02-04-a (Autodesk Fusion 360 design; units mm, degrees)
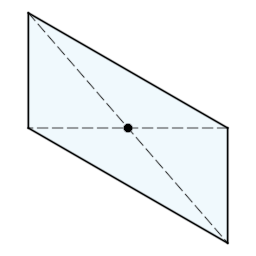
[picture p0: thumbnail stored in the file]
sketch "スケッチ" plane through (0, 0, 0) normal (0, 0, 1) x axis (1, 0, 0)
  line L1 (-50, 25) -> (50, 25)
  line L2 (-50, -25) -> (-50, 25)
  line L3 (50, -25) -> (-50, -25)
  line L4 (50, 25) -> (50, -25)
  line L5 (-50, -25) -> (50, 25)
  line L6 (50, -25) -> (-50, 25)
  point P6 (0, 0)
  point P1 (0, 0)
  point P2 (50, 25)
  point P3 (-50, 25)
  point P5 (50, -25)
  horizontal L1
  perpendicular L1 L2
  parallel L1 L3
  parallel L2 L4
  coincident L5 P6
  coincident L6 P6
  coincident P1 P6
  dimension "d1" distance P2 P3 = 100
  dimension "d2" distance P2 P5 = 50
